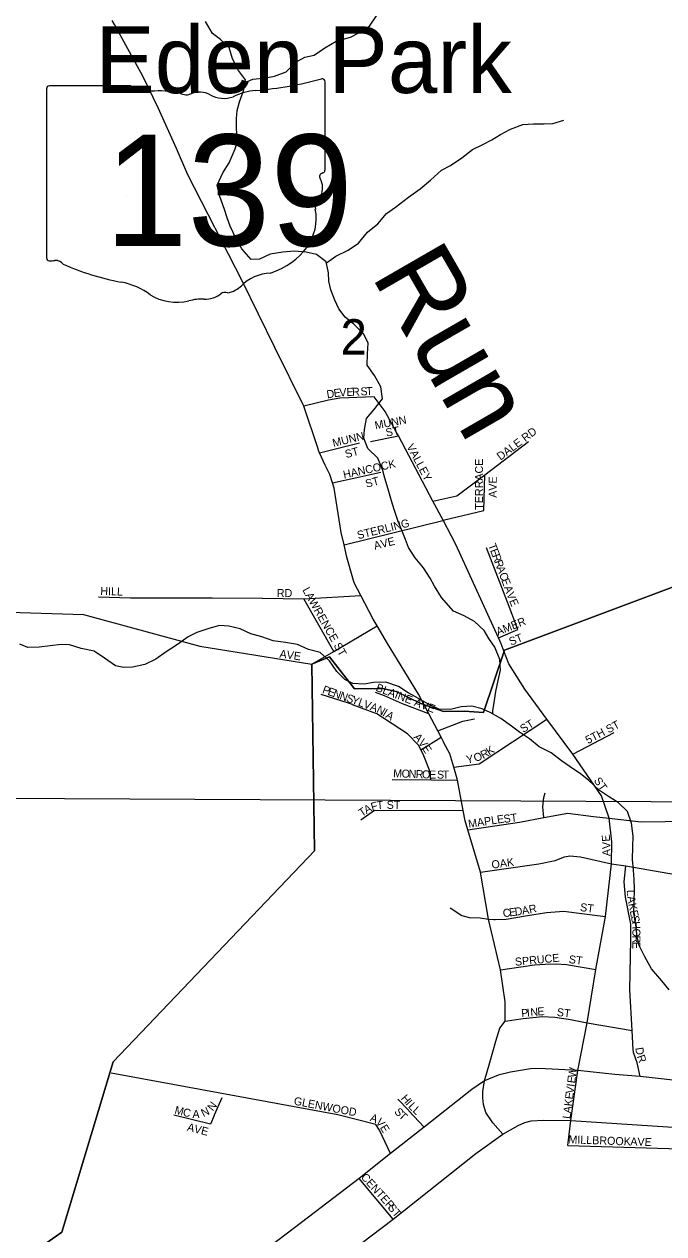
# Model space of a CAD drawing. Extents: x 1624196 to 2029251, y 146837 to 440034.
# Drawn here: x 1842163 to 1846162, y 274356 to 281916 of the extents above; entities that cross this region are included whole.
import ezdxf

# ---------------------------------------------------------------- set-up
doc = ezdxf.new("R2010")
doc.units = 0
for name, color, linetype in [('GM_X_City_Street', 7, 'Continuous'), ('GM_X_City_Street_Text', 7, 'Continuous'), ('GM_X_Corporation', 7, 'Continuous'), ('GM_X_Minor_River', 7, 'Continuous'), ('GM_X_Minor_River_Text', 7, 'Continuous'), ('GM_X_Section', 7, 'Continuous'), ('GM_X_Section_Text', 7, 'Continuous'), ('GM_X_State_Location', 7, 'Continuous'), ('GM_X_State_Route', 7, 'Continuous'), ('GM_X_State_Shield', 7, 'Continuous'), ('GM_X_Unincorporated_Text', 7, 'Continuous'), ('GM_X_US_Route', 7, 'Continuous')]:
    doc.layers.add(name, color=color, linetype=linetype)

msp = doc.modelspace()

# ---------------------------------------------------------------- linework, layer by layer
at = {"layer": 'GM_X_City_Street'}
for points in [[(1844351.6, 279586.3), (1844137.3, 279579.5), (1844066.2, 279565.7), (1843911.3, 279528.5)], [(1845164, 277993.7), (1845164, 277993.9), (1845144.9, 278044), (1845128.2, 278080.7), (1844862.6, 278664.7), (1844782.8, 278815.1), (1844718.6, 278935.8), (1844502.6, 279342.5), (1844488.8, 279368.5), (1844420.1, 279494.5), (1844351.6, 279586.3)], [(1844010.1, 279237.5), (1844258.9, 279298.7)], [(1844327.2, 279308), (1844502.6, 279342.5)], [(1844718.6, 278935.8), (1844868.8, 278967.4), (1845042.6, 279100.4), (1845315.2, 279307.7)], [(1844241.8, 279083.5), (1844241.8, 279083.5), (1844393.4, 279116.7)], [(1844090.2, 279050.2), (1844241.8, 279083.5)], [(1845036.2, 278877.3), (1845042.6, 279100.4)], [(1844162.7, 278662.9), (1844779.3, 278814.2), (1844779.3, 278814.2)], [(1844779.3, 278814.2), (1844782.8, 278815.1), (1845036.2, 278877.3)], [(1845184, 278302.8), (1845184, 278302.8), (1845053.9, 278642.5)], [(1842627.7, 278336.8), (1842828, 278330.7), (1843339.1, 278331.4), (1843651.3, 278328.1), (1843652.8, 278328.1)], [(1843652.8, 278328.1), (1843912.2, 278325.4), (1844267.4, 278345.1)], [(1844098, 277995.2), (1843912.2, 278325.4)], [(1845249, 278132.9), (1845184, 278302.8)], [(1841295.2, 278232.2), (1841804.3, 278248.9), (1842533.4, 278226.4), (1843261.3, 278029.5), (1843961.5, 277915.1), (1844098, 277995.2), (1844370.1, 278154.9)], [(1845128.2, 278080.7), (1845249, 278132.9)], [(1845820.6, 276954.2), (1845773.1, 277093.7), (1845593.2, 277353.2), (1845431.4, 277571.7), (1845293.4, 277760.8), (1845192.5, 277918.7), (1845164, 277993.7)], [(1844216.4, 277662.8), (1844214.8, 277663.4), (1844190.1, 277672.6), (1844020.3, 277726.5)], [(1844693, 277605.7), (1844528.8, 277669), (1844415, 277718.4), (1844359.1, 277739)], [(1844640.2, 277386.5), (1844628.3, 277409.3), (1844558.9, 277480.2), (1844367.8, 277606.5), (1844216.4, 277662.8)], [(1844748.7, 277498.8), (1844904.4, 277560.8), (1844978.7, 277574.1)], [(1844848.5, 277272.2), (1845007.9, 277292.9), (1845431.4, 277571.7)], [(1844643.2, 277380.7), (1844769.4, 277459)], [(1845593.2, 277353.2), (1845851.7, 277488.7)], [(1844706.2, 277192.8), (1844696.9, 277254.1), (1844657.8, 277352.8), (1844643.2, 277380.7), (1844640.6, 277385.7), (1844640.2, 277386.5)], [(1844463.8, 277196.3), (1844706.2, 277192.8), (1844872.1, 277190.4)], [(1845412.6, 276957.2), (1845406, 277024), (1845410.4, 277064.1), (1845412.6, 277082.1), (1845420.9, 277112.1)], [(1844268.8, 276943.6), (1844353.6, 277002.9), (1844907.8, 277002.1)], [(1844936.9, 276880.8), (1845258.7, 276929.3), (1845412.6, 276957.2), (1845561.9, 276984.3), (1845722, 276964.5), (1845820.6, 276954.2)], [(1845581, 275064), (1845624.4, 275375.9), (1845681.6, 275673.5), (1845736.6, 276007), (1845797.6, 276338.6), (1845835.4, 276668.8), (1845836.6, 276805.3), (1845820.6, 276954.2)], [(1845820.6, 276954.2), (1846020.3, 276931.3), (1846467.6, 276936.8)], [(1845016.2, 276615.1), (1845380, 276668.8), (1845483.4, 276688.7), (1845541.1, 276712.5), (1845574.9, 276718.5), (1845640.5, 276712.5), (1845835.4, 276668.8), (1845923.4, 276654.8), (1846365.9, 276579.3), (1846451.3, 276576.6)], [(1845968.5, 275536.8), (1845967.8, 275547.9), (1845963, 275626.4), (1845949.4, 275881), (1845954.7, 276195.4), (1845954.7, 276290.9), (1845922.9, 276459.9), (1845912.9, 276555.4), (1845923.4, 276654.8)], [(1844825.3, 276392.3), (1844898.9, 276344.6), (1844944.6, 276332.7), (1845014.2, 276330.7), (1845065.9, 276322.7), (1845099.7, 276320.7), (1845107.3, 276320.9)], [(1845107.3, 276320.9), (1845177.2, 276322.7), (1845296.5, 276342.6), (1845427.8, 276364.5), (1845537.1, 276372.4), (1845616.6, 276362.5), (1845797.6, 276338.6)], [(1845140, 276005), (1845267.3, 276023.5), (1845353.8, 276036.1), (1845419.8, 276041), (1845487.8, 276043), (1845553.9, 276039), (1845736.6, 276007)], [(1845169.8, 275685.5), (1845281.7, 275701.5), (1845403.1, 275714.3), (1845480.9, 275710), (1845577.8, 275696.2), (1845681.6, 275673.5), (1845963, 275626.4)], [(1846013.7, 275339), (1845995.6, 275423.5), (1845971.4, 275489.9), (1845968.5, 275536.8)], [(1844385.9, 274999.9), (1844384.5, 275002.7), (1844361.3, 275038.3), (1844124.5, 275099.9), (1842707.3, 275359.2)], [(1843399.1, 275205.1), (1843351.6, 275097)], [(1844564.8, 275128), (1844499.4, 275198)], [(1844663, 275023), (1844567.8, 275124.8), (1844564.8, 275128)], [(1843351.6, 275097), (1843351.2, 275096.2), (1843327.3, 275041.8), (1843099.4, 275098.3)], [(1845562.1, 274907.8), (1845581, 275064)], [(1844453, 274857.6), (1844385.9, 274999.9)], [(1845562.1, 274907.8), (1846403.7, 274882.5)], [(1844469.3, 274448.3), (1844257.7, 274701.2)]]:
    msp.add_lwpolyline(points, dxfattribs=at)
at = {"layer": 'GM_X_Corporation'}
for points in [[(1841114.9, 273467), (1842398.8, 274366.7), (1842719.2, 275429.7), (1843977.5, 276748.7), (1843961.5, 277915.1), (1844072.2, 277961.5), (1844229.2, 277762.7), (1844403.2, 277764), (1844488.9, 277744.6), (1844641.8, 277670.1), (1844785, 277619.8), (1844913, 277621.8), (1845034.9, 277613.9), (1845165.9, 278003), (1846548.6, 278522)], [(1846548.6, 278522), (1845165.9, 278003), (1845034.9, 277613.9), (1844913, 277621.8), (1844785, 277619.8), (1844641.8, 277670.1), (1844488.9, 277744.6), (1844403.2, 277764), (1844229.2, 277762.7), (1844072.2, 277961.5), (1843961.5, 277915.1), (1843977.5, 276748.7), (1842719.2, 275429.7), (1842398.8, 274366.7), (1841114.9, 273467)]]:
    msp.add_lwpolyline(points, dxfattribs=at)
at = {"layer": 'GM_X_Minor_River'}
for points in [[(1845092.2, 277604.2), (1845093.5, 277625), (1845101.4, 277677.1), (1845111.2, 277745.2), (1845127.1, 277813.4), (1845140.9, 277879.5), (1845136.8, 277945.6), (1845104.6, 278021.6), (1845068.5, 278075.6), (1845038.4, 278125.6), (1844978.3, 278183.6), (1844914.3, 278217.5), (1844846.2, 278247.3), (1844772.1, 278333.3), (1844727.9, 278403.3), (1844701.8, 278453.3), (1844659.7, 278517.3), (1844607.6, 278581.3), (1844565.5, 278645.3), (1844547.4, 278695.3), (1844521.2, 278757.3), (1844501.1, 278807.4), (1844477, 278883.4), (1844458.8, 278937.5), (1844438.7, 279009.5), (1844418.5, 279079.6), (1844402.4, 279133.6), (1844374.3, 279203.6), (1844312.2, 279263.6), (1844286, 279329.6), (1844289.9, 279383.7), (1844303.8, 279451.8), (1844349.6, 279506), (1844403.4, 279574.3), (1844393.3, 279648.4), (1844353.1, 279720.4), (1844307, 279784.4), (1844308.8, 279856.5), (1844312.7, 279922.6), (1844286.6, 279978.6), (1844224.4, 280040.5), (1844170.4, 280084.5), (1844130.3, 280136.5), (1844104.2, 280190.5), (1844080, 280256.5), (1844067.9, 280310.6), (1844065.8, 280362.6), (1844051.6, 280430.7), (1843989.6, 280476.6), (1843925.6, 280490.5), (1843851.6, 280498.3), (1843779.6, 280490.2), (1843701.7, 280478), (1843633.8, 280447.8), (1843581.8, 280445.6), (1843523.7, 280511.6), (1843485.6, 280577.6), (1843451.4, 280653.6), (1843431.3, 280705.6), (1843415.2, 280757.7), (1843387, 280839.8), (1843368.9, 280909.8), (1843404.7, 280986), (1843444.5, 281050.2), (1843482.3, 281136.4), (1843498.2, 281190.5), (1843490, 281258.6), (1843489.9, 281326.7), (1843493.8, 281376.8), (1843509.6, 281430.9), (1843533.5, 281499.1), (1843547.3, 281567.2), (1843503.2, 281627.2), (1843465, 281699.2), (1843444.9, 281769.3), (1843390.8, 281819.2), (1843340.7, 281857.2), (1843296.6, 281933.2)], [(1843544, 281551.1), (1843593.3, 281571.3), (1843673.2, 281581.5), (1843729.1, 281591.7), (1843801.1, 281617.9), (1843856.9, 281676.1), (1843916.8, 281710.3), (1843976.7, 281722.5), (1844042.6, 281768.7), (1844114.4, 281808.9), (1844202.3, 281835.2), (1844254.3, 281861.3), (1844322.1, 281903.6), (1844366, 281967.8)], [(1844053, 280424.1), (1844111.5, 280466.9), (1844189.4, 280503.1), (1844253.3, 280547.4), (1844309.1, 280615.6), (1844374.9, 280667.8), (1844428.8, 280732.1), (1844484.6, 280772.3), (1844566.4, 280834.5), (1844638.3, 280886.8), (1844704.1, 280941), (1844772, 281003.3), (1844827.9, 281033.5), (1844899.7, 281079.7), (1844965.6, 281131.9), (1845029.5, 281164.1), (1845087.4, 281192.3), (1845141.3, 281226.5), (1845203.2, 281260.7), (1845281, 281288.9), (1845347, 281293.1), (1845413, 281293.2), (1845466.9, 281295.4), (1845536.9, 281315.6)], [(1846195, 275881), (1846148.9, 275937), (1846084.7, 276011), (1846042.6, 276087), (1846008.4, 276157), (1845994.3, 276211.1), (1845986.1, 276289.2), (1845974, 276357.2), (1845975.8, 276431.3), (1845977.6, 276509.5), (1845975.5, 276569.5), (1845971.4, 276627.6), (1845965.2, 276695.7), (1845967, 276773.8), (1845970.9, 276841.9), (1845958.7, 276922), (1845934.5, 276996.1), (1845876.4, 277052), (1845822.4, 277084), (1845760.3, 277125.9), (1845690.2, 277191.8), (1845640.2, 277229.7), (1845576.1, 277273.6), (1845522, 277311.6), (1845458, 277361.5), (1845381.9, 277399.4), (1845321.8, 277449.3), (1845259.8, 277491.2), (1845209.7, 277529.1), (1845143.6, 277577.1), (1845075.6, 277613), (1845025.5, 277636.9), (1844961.5, 277652.7), (1844895.6, 277648.6), (1844827.6, 277632.4), (1844755.7, 277634.2), (1844687.6, 277668.1), (1844613.6, 277710), (1844563.5, 277737.9), (1844503.5, 277775.8), (1844423.5, 277803.7), (1844347.5, 277801.5), (1844289.6, 277791.3), (1844217.6, 277795.2), (1844167.6, 277821.1), (1844117.5, 277871), (1844071.3, 277937), (1844013.2, 277989), (1843941.2, 278006.8), (1843871.2, 278038.7), (1843797.2, 278050.6), (1843719.2, 278062.4), (1843649.2, 278086.3), (1843579.2, 278106.1), (1843513.2, 278136), (1843443.2, 278153.9), (1843385.2, 278157.7), (1843317.3, 278139.5), (1843243.4, 278113.3), (1843189.4, 278087.2), (1843121.6, 278038.9), (1843051.7, 277992.7), (1842985.9, 277946.5), (1842918, 277914.3), (1842840.1, 277898), (1842786.1, 277895.9), (1842734.1, 277905.8), (1842666, 277953.7), (1842599.9, 277997.6), (1842520, 278013.5), (1842445.9, 278037.3), (1842394, 278039.2), (1842326, 278031), (1842256.1, 278022.8), (1842186.1, 278020.7), (1842136.1, 278040.6)]]:
    msp.add_lwpolyline(points, dxfattribs=at)
at = {"layer": 'GM_X_Section'}
msp.add_lwpolyline([(1841711.4, 282290.1), (1846841.1, 282183.3), (1846488.4, 277052.7), (1841192.2, 277080.3)], close=True, dxfattribs=at)
at = {"layer": 'GM_X_State_Route'}
for points in [[(1844000.7, 279260.9), (1843911.3, 279528.5), (1843729.4, 279895.6), (1843525.8, 280311.5), (1843187.1, 280973.9), (1843114.9, 281138.7), (1843000.8, 281394), (1842906, 281590.5), (1842727, 281913.8), (1842713.9, 281939.9)], [(1844786.9, 277425.2), (1844784.2, 277430.6), (1844769.4, 277459), (1844748.7, 277498.8), (1844693, 277605.7), (1844628.9, 277729), (1844433.7, 278045), (1844370.1, 278154.9), (1844345.1, 278198), (1844267.4, 278345.1), (1844225.1, 278425.3), (1844180.5, 278583.9), (1844162.7, 278662.9), (1844145.8, 278738.4), (1844100.1, 279017.1), (1844090.2, 279050.2), (1844074.9, 279101.4), (1844045.4, 279159.8), (1844010.1, 279237.5), (1844004.1, 279250.8), (1844000.7, 279260.9)], [(1845075, 275426.6), (1845112.3, 275559.8), (1845137.1, 275640.6), (1845169.8, 275685.5), (1845169.8, 275804.9), (1845140, 276005), (1845065.9, 276322.7), (1845016.2, 276615.1), (1844936.9, 276880.8), (1844920, 276937.5), (1844907.8, 277002.1), (1844872.1, 277190.4), (1844870.2, 277200.3), (1844848.5, 277272.2), (1844823.6, 277354.9), (1844786.9, 277425.2)], [(1845154.4, 274978.5), (1845092.3, 275048.8), (1845049, 275114.5), (1845033.7, 275163.7), (1845030.2, 275205.9), (1845030.2, 275245.8), (1845040.8, 275312.6), (1845075, 275426.6)]]:
    msp.add_lwpolyline(points, dxfattribs=at)
at = {"layer": 'GM_X_State_Shield'}
for p, q in [((1844043.9, 281003.7), (1844043.9, 281556.4)), ((1842303.7, 281512), (1842303.7, 280455.4)), ((1842830.4, 281530.2), (1842320.8, 281530.2)), ((1844043.7, 281003.8), (1844043.9, 281003.7))]:
    msp.add_line(p, q, dxfattribs=at)
for centre, major_axis, start_param, end_param in [((1843424, 282970.8), (1845.5, 0), 4.814394, 5.042369), ((1844024.6, 281558.7), (19.4, 0), 6.141152, 7.989035), ((1842323.6, 281514.3), (20.2, 0), 1.712693, 3.28349), ((1842951.8, 281652.9), (195.5, 0), 4.042523, 4.731795), ((1843016.6, 280937), (702, 0), 1.404758, 1.657858), ((1843176, 281519.8), (56.4, 0), 3.836095, 5.185415), ((1843258.8, 281397.6), (117.3, 0), 0.950623, 2.079405), ((1843410.2, 281565.1), (141.1, 0), 4.081561, 5.145723), ((1843659.4, 281207.5), (371.3, 0), 1.699011, 2.107814), ((1844039.4, 280963.1), (30, 0), 1.883978, 3.671073), ((1843848.7, 280893.2), (180, 0), 5.934695, 6.695948), ((1844023.2, 281001.5), (20.7, 0), 5.05454, 6.418171), ((1844113.3, 280772.3), (130.9, 0), 2.387724, 3.262537), ((1843527.4, 280702), (461.6, 0), 5.101752, 6.440018), ((1842323.8, 280453.1), (20.3, 0), 3.00124, 4.508301), ((1842326.9, 280561.2), (155.2, 0), 4.665946, 4.897461), ((1842358.6, 280394.4), (56, 0), 0.519207, 1.627899), ((1843065.2, 281343.8), (1332.7, 0), 4.195997, 4.488961), ((1843722, 280158.7), (252.8, 0), 1.647645, 2.488434), ((1842667.9, 279980.7), (417, 0), 0.823519, 1.323587), ((1843401.7, 280353), (149.1, 0), 4.937069, 5.64225), ((1843118.9, 280389.2), (264.6, 0), 4.026481, 4.996735), ((1843271.8, 280023.9), (217.4, 0), 1.495662, 1.94098), ((1843291.1, 280310.1), (141, 0), 4.691044, 5.507374), ((1843418.6, 280207.7), (39.7, 0), 1.147584, 2.315152)]:
    msp.add_ellipse(centre, major_axis=major_axis, ratio=0.8, start_param=start_param, end_param=end_param, dxfattribs=at)
at = {"layer": 'GM_X_US_Route'}
for points in [[(1846331.3, 275303.1), (1846013.7, 275339), (1845855.5, 275352.3), (1845624.4, 275375.9), (1845383, 275389.9), (1845329.1, 275387.6), (1845277.5, 275379.4), (1845202.5, 275366.5), (1845126.3, 275346.6), (1845040.8, 275312.6)], [(1845040.8, 275312.6), (1844962.3, 275258.6), (1844663, 275023), (1844453, 274857.6), (1844257.7, 274701.2), (1843939.7, 274458.9)], [(1845154.4, 274978.5), (1845250.5, 275032.4), (1845293.9, 275052.3), (1845332.6, 275061.7), (1845408.7, 275066.4), (1845581, 275064), (1846378.6, 275011.3)], [(1840011.1, 271313.1), (1840144.6, 271398.1), (1840417.7, 271583.5), (1840672.8, 271756.9), (1840857.3, 271878.5), (1841265.3, 272147.3), (1841296.2, 272168.1), (1841686.8, 272432.5), (1841736.5, 272466), (1842201.1, 272779.2), (1842325.3, 272867.5), (1842616.7, 273074.6), (1843015.6, 273369.1), (1843773.9, 273915.8), (1844202.8, 274244.3), (1844469.3, 274448.3), (1844986.8, 274857.6), (1845154.4, 274978.5)], [(1843939.7, 274458.9), (1843566.3, 274174.3), (1842837.6, 273629), (1842242.3, 273195.7)]]:
    msp.add_lwpolyline(points, dxfattribs=at)

# ---------------------------------------------------------------- texts
at = {"layer": 'GM_X_City_Street_Text'}
for s, rotation, p in [('S', 2.39038, (1844266.5, 279595.5)), ('T', 2.39038, (1844301.7, 279597)), ('D', 9.32939, (1844058, 279576.9)), ('E', 8.29433, (1844101.2, 279584)), ('V', 3.81626, (1844135, 279588.9)), ('E', 2.41893, (1844178.6, 279591.9)), ('R', 2.39302, (1844213.8, 279593.3)), ('MUNN', 10.78358, (1844359.5, 279383.5)), ('MUNN', 13.70714, (1844097, 279273.2)), ('ST', 10.61883, (1844427.7, 279338.1)), ('DALE RD', 36.87062, (1845141.1, 279187.4)), ('ST', 14.93096, (1844176.2, 279203.2)), ('VALLEY', 297.95105, (1844551.9, 279277.2)), ('HANCOCK', 12.43889, (1844162.9, 279075.1)), ('TERRACE', 90, (1845031.4, 278881.2)), ('ST', 14.93096, (1844303.7, 279018.4)), ('AVE', 90, (1845117.4, 278956)), ('STERLING', 13.82955, (1844251, 278696.7)), ('AVE', 14.03624, (1844355.4, 278630.9)), ('T', 290.57364, (1845062.8, 278660.1)), ('E', 290.54806, (1845075.2, 278627.2)), ('R', 290.56291, (1845087.5, 278594.2)), ('R', 290.57027, (1845101.5, 278557.1)), ('A', 290.56757, (1845115.4, 278520)), ('C', 290.54778, (1845130.8, 278478.9)), ('E', 290.58327, (1845144.7, 278441.7)), ('HILL', 358.21116, (1842638.7, 278348.8)), ('RD', 0.00001, (1843742.8, 278335.6)), ('LAWRENCE ST', 299.45356, (1843900.6, 278379.8)), ('A', 290.56223, (1845161.7, 278396.4)), ('V', 290.87266, (1845177.3, 278355)), ('E', 293.24389, (1845193.8, 278311.7)), ('AMER', 22.06776, (1845125.3, 278093.5)), ('ST', 21.80392, (1845205.7, 278031.3)), ('AVE', 352.14707, (1843757.3, 277957.7)), ('P', 340.44175, (1844023.1, 277737.3)), ('E', 340.44742, (1844056.3, 277725.5)), ('N', 340.44632, (1844089.5, 277713.7)), ('BLAINE AVE', 338.96362, (1844357.3, 277750.6)), ('N', 340.44632, (1844130.9, 277699)), ('S', 340.44742, (1844172.4, 277684.3)), ('Y', 340.44632, (1844205.6, 277672.5)), ('L', 340.42888, (1844247, 277657.7)), ('V', 340.44632, (1844280.2, 277646)), ('A', 339.72279, (1844321.5, 277631.3)), ('N', 332.02716, (1844361.1, 277616.8)), ('I', 328.54143, (1844399.3, 277596.5)), ('A', 328.23787, (1844418, 277585.1)), ('ST', 31.60468, (1845282.3, 277485.6)), ('5TH ST', 27.69883, (1845687.6, 277415.5)), ('A', 311.55912, (1844594.5, 277457.6)), ('V', 306.57049, (1844623, 277425.5)), ('E', 301.86348, (1844648.6, 277391.1)), ('R', 28.70843, (1845032.5, 277322.6)), ('K', 33.18168, (1845070.9, 277343.9)), ('Y', 10.81544, (1844931.9, 277293.8)), ('O', 19.76193, (1844983.3, 277304.3)), ('M', 357.89609, (1844469.2, 277209.8)), ('O', 357.89063, (1844521.9, 277207.9)), ('N', 357.89063, (1844565.9, 277206.3)), ('R', 357.88699, (1844609.9, 277204.6)), ('O', 357.97744, (1844649.6, 277203.2)), ('E', 359.14124, (1844694.6, 277201.6)), ('S', 359.97068, (1844743.8, 277201)), ('T', 359.99563, (1844779, 277201)), ('ST', 304.69079, (1845721.7, 277188.2)), ('T', 33.69567, (1844274.1, 276960.2)), ('A', 28.07972, (1844302.3, 276979)), ('F', 16.84783, (1844338.7, 276998.7)), ('T', 5.61594, (1844369.8, 277008.4)), ('ST', 0.00001, (1844429.2, 277011.8)), ('MAPLE', 8.47095, (1844942.6, 276892.9)), ('ST', 7.12838, (1845162.9, 276923.7)), ('E', 94.86927, (1845826.7, 276809)), ('V', 91.0521, (1845827.7, 276761.4)), ('OAK', 7.59703, (1845088, 276637.7)), ('A', 90.08743, (1845827.8, 276716.4)), ('L', 272.04932, (1845930.2, 276504.7)), ('D', 7.39991, (1845232.6, 276343.8)), ('A', 10.12495, (1845278.8, 276349.9)), ('R', 11.82942, (1845323.7, 276357.9)), ('ST', 352.87835, (1845636, 276373.7)), ('A', 279.02322, (1845932.1, 276462.9)), ('K', 281.49619, (1845939.4, 276417.2)), ('C', 7.4021, (1845158.4, 276334.2)), ('E', 7.39608, (1845197.7, 276339.3)), ('E', 281.46799, (1845948.2, 276374.1)), ('S', 281.3019, (1845955.2, 276339.6)), ('H', 274.48504, (1845961.9, 276306.6)), ('O', 270.19672, (1845965.3, 276263.8)), ('R', 270, (1845965.4, 276219.8)), ('E', 269.99561, (1845965.4, 276180.2)), ('SPRUCE', 5.49192, (1845233.5, 276030.6)), ('ST', 352.87162, (1845565.6, 276048.2)), ('P', 5.83023, (1845273, 275709.4)), ('I', 5.83417, (1845308, 275712.9)), ('N', 5.82368, (1845329.9, 275715.2)), ('E', 4.73188, (1845373.4, 275719.6)), ('ST', 352.88003, (1845490.8, 275718.1)), ('D', 278.97548, (1845983.2, 275517.6)), ('R', 289.02183, (1845992.3, 275465)), ('E', 82.49201, (1845606.4, 275294.5)), ('W', 81.44428, (1845610.9, 275329.1)), ('V', 82.49051, (1845597.8, 275229)), ('I', 82.50356, (1845603.5, 275272.7)), ('GLENWOOD', 349.24988, (1843845.7, 275163.7)), ('H', 311.31957, (1844515.5, 275200.2)), ('I', 311.28872, (1844544.5, 275167.1)), ('K', 82.50356, (1845587.4, 275150.5)), ('E', 82.49201, (1845593.2, 275194.2)), ('M', 345.73475, (1843100.2, 275107.9)), ('C', 345.73475, (1843151.4, 275094.9)), ('A', 358.98408, (1843215.1, 275080.2)), ('N', 25.48274, (1843283.5, 275084.8)), ('N', 51.98139, (1843342.8, 275119.3)), ('S', 312.21672, (1844473.5, 275116.3)), ('T', 316.73269, (1844500.2, 275087.2)), ('L', 313.86138, (1844560.7, 275148.8)), ('L', 317.84889, (1844587.8, 275120.9)), ('A', 82.49667, (1845581.7, 275106.9)), ('AVE', 345.96376, (1843178.6, 275000.9)), ('A', 339.77136, (1844321.1, 275062.5)), ('V', 312.02377, (1844357.2, 275050.8)), ('E', 300.61933, (1844385.1, 275020.2)), ('L', 82.49201, (1845577.1, 275072)), ('MILLBROOK', 357.9298, (1845564.8, 274921.8)), ('AVE', 358.02636, (1845951.9, 274908.6)), ('CENTER', 311.98737, (1844264.6, 274707.5)), ('ST', 310.23938, (1844432, 274518.1))]:
    msp.add_text(s, height=50, rotation=rotation, dxfattribs=at).set_placement(p)
at = {"layer": 'GM_X_Minor_River_Text'}
msp.add_text('Run', height=500, rotation=299.99998, dxfattribs=at).set_placement((1844328.4, 280345.9))
at = {"layer": 'GM_X_Section_Text'}
msp.add_text('2', height=221, rotation=0.00001, dxfattribs=at).set_placement((1844141, 279851.2))
at = {"layer": 'GM_X_State_Location'}
for s in ['s', 'r']:
    msp.add_text(s, height=1, dxfattribs=at).set_placement((1843154.2, 280913.5))
msp.add_text('139', height=1, rotation=0.00001, dxfattribs=at).set_placement((1842801.2, 280840.7))
at = {"layer": 'GM_X_State_Shield'}
msp.add_text('139', height=696.1, dxfattribs=at).set_placement((1842666.3, 280529.9))
at = {"layer": 'GM_X_Unincorporated_Text'}
msp.add_text('Eden Park', height=417, rotation=0.00001, dxfattribs=at).set_placement((1842607.6, 281485.8))

doc.saveas('drawing.dxf')
